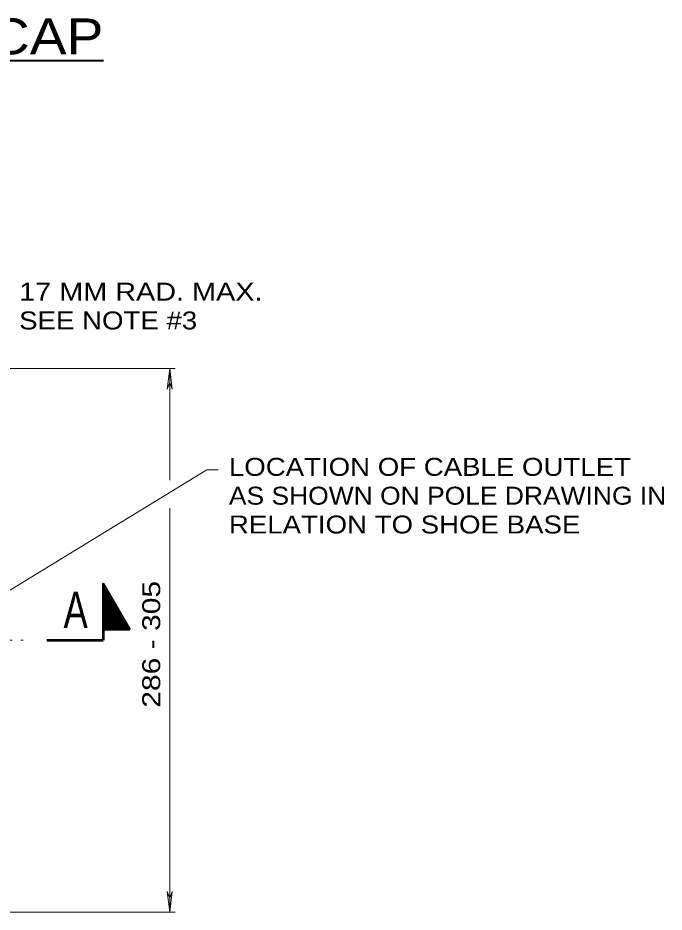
# Model space of a CAD drawing. Extents: x 312583 to 312854, y 144419 to 144597.
# Drawn here: x 312736.4 to 312763.75, y 144508.76 to 144546.6 of the extents above; entities that cross this region are included whole.
import ezdxf
from ezdxf.enums import TextEntityAlignment as Align

# ---------------------------------------------------------------- set-up
doc = ezdxf.new("R2010")
doc.units = 0
doc.header["$LTSCALE"] = 0.3
doc.linetypes.add('DOTTED', pattern=[1.5, 0.3, -1.2])
doc.layers.add('2', color=7, linetype='Continuous', lineweight=13)

msp = doc.modelspace()

# ---------------------------------------------------------------- linework, layer by layer
at = {"layer": '2', "lineweight": 40}
msp.add_line((312715.4253, 144544.8043), (312740.0175, 144544.8043), dxfattribs=at)
at = {"layer": '2'}
for p, q in [((312734.3724, 144531.7639), (312743.0587, 144531.7639)), ((312742.8211, 144531.7639), (312742.7137, 144530.8975)), ((312742.8211, 144531.7639), (312742.9284, 144530.8975)), ((312742.8211, 144527.0412), (312742.8211, 144531.7639)), ((312742.7137, 144530.8975), (312742.8211, 144531.1735)), ((312742.9284, 144530.8975), (312742.8211, 144531.1735)), ((312742.8211, 144508.7639), (312742.8211, 144525.8605)), ((312742.7137, 144509.6302), (312742.8211, 144509.3542)), ((312742.8211, 144508.7639), (312742.7137, 144509.6302)), ((312742.9284, 144509.6302), (312742.8211, 144509.3542)), ((312742.8211, 144508.7639), (312742.9284, 144509.6302)), ((312734.4031, 144508.7639), (312743.0587, 144508.7639))]:
    msp.add_line(p, q, dxfattribs=at)
at = {"layer": '2', "lineweight": 35}
for p, q in [((312740.0074, 144522.6405), (312740.0227, 144522.6405)), ((312740.0074, 144522.6099), (312740.0304, 144522.6175)), ((312740.0074, 144522.5792), (312740.0457, 144522.6022)), ((312740.0074, 144522.5562), (312740.0534, 144522.5792)), ((312740.0074, 144522.5255), (312740.0687, 144522.5562)), ((312740.0074, 144522.5025), (312740.0764, 144522.5409)), ((312740.0074, 144522.4719), (312740.0917, 144522.5179)), ((312740.0074, 144522.4412), (312740.0994, 144522.4949)), ((312740.0074, 144522.4105), (312740.1147, 144522.4795)), ((312740.0074, 144522.3875), (312740.1224, 144522.4565)), ((312740.0074, 144522.3645), (312740.1377, 144522.4335)), ((312740.0074, 144522.3339), (312740.1454, 144522.4105)), ((312740.0074, 144522.3109), (312740.1607, 144522.3952)), ((312740.0074, 144522.2802), (312740.1761, 144522.3722)), ((312740.0074, 144522.2495), (312740.1837, 144522.3492)), ((312740.0074, 144522.2189), (312740.1991, 144522.3339)), ((312740.0074, 144522.1959), (312740.2144, 144522.3109)), ((312740.0074, 144522.1652), (312740.2221, 144522.2879)), ((312740.0074, 144522.1422), (312740.2374, 144522.2725)), ((312740.0074, 144522.1115), (312740.2451, 144522.2495)), ((312740.0074, 144522.0809), (312740.2604, 144522.2265)), ((312740.0074, 144522.0579), (312740.2681, 144522.2112)), ((312740.0074, 144522.0272), (312740.2834, 144522.1805)), ((312740.0074, 144522.0042), (312740.2911, 144522.1652)), ((312740.0074, 144521.9735), (312740.3064, 144522.1422)), ((312740.0074, 144521.9429), (312740.3141, 144522.1192)), ((312740.0074, 144521.9199), (312740.3294, 144522.1039)), ((312740.0074, 144521.8892), (312740.3371, 144522.0809)), ((312740.0074, 144521.8662), (312740.3524, 144522.0579)), ((312740.0074, 144521.8355), (312740.3677, 144522.0425)), ((312740.0074, 144521.8125), (312740.3754, 144522.0195)), ((312740.0074, 144521.7819), (312740.3907, 144521.9965)), ((312740.0074, 144521.7512), (312740.4061, 144521.9812)), ((312740.0074, 144521.7205), (312740.4137, 144521.9582)), ((312740.0074, 144521.6975), (312740.4291, 144521.9352)), ((312740.0074, 144521.6745), (312740.4367, 144521.9122)), ((312740.0074, 144521.6439), (312740.4521, 144521.8969)), ((312740.0074, 144521.6132), (312740.4597, 144521.8739)), ((312740.0074, 144521.5902), (312740.4751, 144521.8509)), ((312740.0074, 144521.5595), (312740.4827, 144521.8355)), ((312740.0074, 144521.5289), (312740.4981, 144521.8125)), ((312740.0074, 144521.5059), (312740.5057, 144521.7895)), ((312740.0074, 144521.4752), (312740.5211, 144521.7742)), ((312740.0074, 144521.4445), (312740.5287, 144521.7512)), ((312740.0074, 144521.4215), (312740.5441, 144521.7282)), ((312740.0074, 144521.3679), (312740.5671, 144521.6822)), ((312740.0151, 144521.3909), (312740.5594, 144521.7129)), ((312740.0074, 144521.3372), (312740.5824, 144521.6669)), ((312740.0074, 144521.3142), (312740.5901, 144521.6439)), ((312740.0074, 144521.2835), (312740.6054, 144521.6209)), ((312740.0074, 144521.2529), (312740.6131, 144521.6055)), ((312740.0074, 144521.2222), (312740.6284, 144521.5825)), ((312740.0074, 144521.1992), (312740.6361, 144521.5595)), ((312740.0074, 144521.1762), (312740.6514, 144521.5442)), ((312740.0074, 144521.1149), (312740.6744, 144521.4982)), ((312740.0074, 144521.0919), (312740.6821, 144521.4829)), ((312740.0074, 144521.0612), (312740.6974, 144521.4599)), ((312740.0074, 144521.0305), (312740.7127, 144521.4369)), ((312740.0074, 144521.0075), (312740.7204, 144521.4139)), ((312740.0074, 144520.9769), (312740.7357, 144521.3985)), ((312740.0074, 144520.9462), (312740.7511, 144521.3755)), ((312740.0074, 144520.8695), (312740.7817, 144521.3142)), ((312740.0151, 144521.1455), (312740.6591, 144521.5212)), ((312740.0151, 144520.9232), (312740.7587, 144521.3525)), ((312740.0151, 144520.8925), (312740.7741, 144521.3372)), ((312740.0074, 144520.8389), (312740.7971, 144521.2912)), ((312740.0074, 144520.8159), (312740.8047, 144521.2759)), ((312740.0074, 144520.7852), (312740.8201, 144521.2529)), ((312740.0074, 144520.7545), (312740.8277, 144521.2299)), ((312740.0304, 144520.7392), (312740.8431, 144521.2145)), ((312740.0841, 144520.7392), (312740.8507, 144521.1839)), ((312740.1224, 144520.7392), (312740.8661, 144521.1685)), ((312740.1761, 144520.7392), (312740.8737, 144521.1455)), ((312740.2221, 144520.7392), (312740.8891, 144521.1225)), ((312740.2681, 144520.7392), (312740.9044, 144521.1072)), ((312740.3141, 144520.7392), (312740.9121, 144521.0842)), ((312740.3677, 144520.7392), (312740.9274, 144521.0612)), ((312740.4137, 144520.7392), (312740.9427, 144521.0459)), ((312740.4597, 144520.7392), (312740.9504, 144521.0229)), ((312740.5134, 144520.7392), (312740.9657, 144521.0075)), ((312740.5594, 144520.7392), (312740.9734, 144520.9845)), ((312740.6054, 144520.7392), (312740.9887, 144520.9615)), ((312740.6591, 144520.7392), (312740.9964, 144520.9462)), ((312740.7051, 144520.7392), (312741.0117, 144520.9155)), ((312740.7511, 144520.7392), (312741.0194, 144520.9002)), ((312740.7971, 144520.7392), (312741.0347, 144520.8772)), ((312740.8507, 144520.7392), (312741.0424, 144520.8542)), ((312740.8891, 144520.7392), (312741.0577, 144520.8389)), ((312740.9427, 144520.7392), (312741.0654, 144520.8159)), ((312740.9887, 144520.7392), (312741.0807, 144520.7929)), ((312741.0424, 144520.7392), (312741.0961, 144520.7775)), ((312741.0884, 144520.7392), (312741.1037, 144520.7545))]:
    msp.add_line(p, q, dxfattribs=at)
at = {"layer": '2', "lineweight": 53}
for p in [(312740.0074, 144520.7392), (312737.6154, 144520.2639)]:
    msp.add_line(p, (312740.0074, 144520.2639), dxfattribs=at)
at = {"layer": '2', "linetype": 'DOTTED'}
msp.add_line((312725.9391, 144520.2639), (312736.9484, 144520.2639), dxfattribs=at)
at = {"layer": '2'}
msp.add_lwpolyline([(312732.6627, 144520.3099), (312744.3927, 144527.4782), (312744.8757, 144527.4782)], dxfattribs=at)
at = {"layer": '2', "lineweight": 53}
msp.add_lwpolyline([(312740.0074, 144520.7392), (312741.1191, 144520.7392), (312740.0074, 144522.6559)], close=True, dxfattribs=at)

# ---------------------------------------------------------------- texts
at = {"layer": '2'}
for s, height, width, p in [('CAST ALUMINUM CAP', 1.52, 1.15, (312727.6148, 144545.0587)), ('A', 1.533, 0.75, (312738.842, 144520.7852))]:
    msp.add_text(s, height=height, dxfattribs=dict(at, width=width)).set_placement(p, align=Align.CENTER)
for s, width, p in [('17 MM RAD. MAX.', 1.2, (312736.4501, 144534.6379)), ('SEE NOTE #3', 1.15, (312736.4501, 144533.4179)), ('LOCATION OF CABLE OUTLET', 1.15, (312745.3281, 144527.2242)), ('AS SHOWN ON POLE DRAWING IN', 1.1, (312745.3281, 144526.0042)), ('RELATION TO SHOE BASE', 1.15, (312745.3281, 144524.7842))]:
    msp.add_text(s, height=0.76, dxfattribs=dict(at, width=width)).set_placement(p)
at = {"layer": '2', "width": 1.25}
msp.add_text('286 - 305', height=0.76, rotation=90, dxfattribs=at).set_placement((312742.4205, 144517.4106))

doc.saveas('drawing.dxf')
